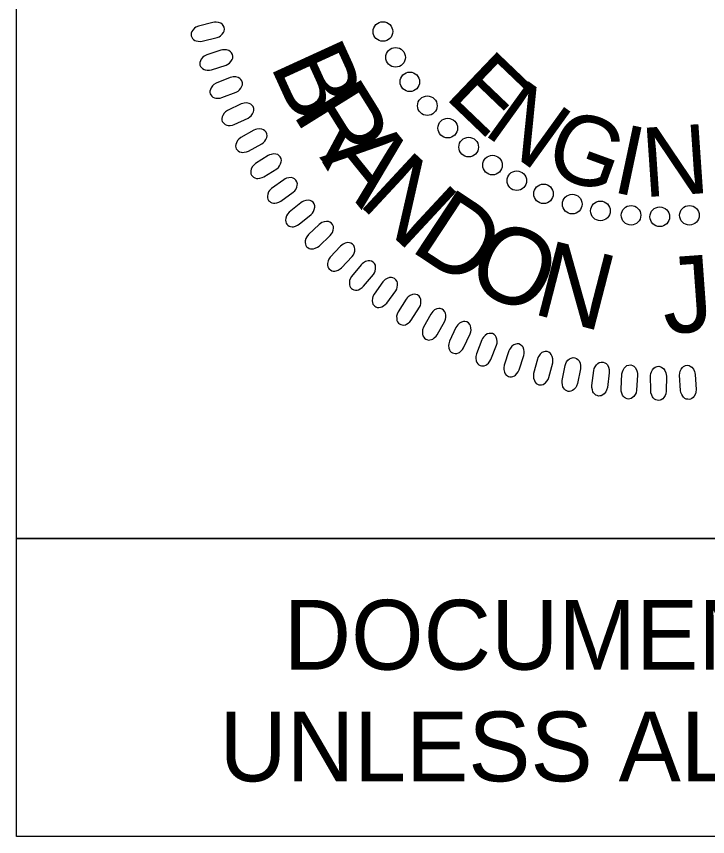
# Model space of a CAD drawing. Extents: x 18938 to 19565, y 6931 to 7973.
# Drawn here: x 19353.14 to 19360.49, y 7788.04 to 7796.76 of the extents above; entities that cross this region are included whole.
import ezdxf

# ---------------------------------------------------------------- set-up
doc = ezdxf.new("R2010")
doc.units = 0
for name, color, linetype in [('Old_Level_10', 7, 'Continuous'), ('Prop Pavement Schedule Description CELL', 7, 'Continuous'), ('Typical Hinge Slope Interstate CELL', 7, 'Continuous'), ('Typical Pavement Slope Information CELL', 7, 'Continuous')]:
    doc.layers.add(name, color=color, linetype=linetype)

# ---------------------------------------------------------------- blocks, each defined once
blk = doc.blocks.new('Brandon J. McInnis')
at = {"layer": 'Old_Level_10'}
for points in [[(-87.757, 42.228), (-88.945, 41.923), (-89.148, 41.832), (-89.271, 41.747), (-89.407, 41.596), (-89.489, 41.475), (-89.538, 41.346), (-89.551, 41.235), (-89.542, 41.121), (-89.495, 41.018), (-89.437, 40.91), (-89.353, 40.823), (-89.23, 40.747), (-89.138, 40.708), (-88.976, 40.68), (-88.787, 40.667), (-88.628, 40.685), (-87.408, 40.989), (-87.249, 41.053), (-87.126, 41.132), (-86.993, 41.258), (-86.886, 41.401), (-86.833, 41.515), (-86.814, 41.682), (-86.832, 41.832), (-86.907, 41.967), (-86.982, 42.056), (-87.11, 42.155), (-87.304, 42.228), (-87.495, 42.249), (-87.627, 42.245)], [(-87.103, 39.944), (-88.269, 39.565), (-88.467, 39.462), (-88.584, 39.37), (-88.71, 39.21), (-88.785, 39.083), (-88.826, 38.952), (-88.831, 38.841), (-88.816, 38.728), (-88.762, 38.628), (-88.696, 38.523), (-88.608, 38.442), (-88.48, 38.374), (-88.386, 38.341), (-88.223, 38.323), (-88.034, 38.322), (-87.875, 38.349), (-86.677, 38.73), (-86.523, 38.804), (-86.404, 38.89), (-86.281, 39.024), (-86.182, 39.174), (-86.136, 39.291), (-86.128, 39.459), (-86.155, 39.607), (-86.239, 39.737), (-86.319, 39.821), (-86.452, 39.911), (-86.651, 39.973), (-86.842, 39.981), (-86.975, 39.969)], [(-86.344, 37.707), (-87.485, 37.256), (-87.675, 37.14), (-87.786, 37.04), (-87.902, 36.873), (-87.969, 36.742), (-88.001, 36.609), (-88, 36.497), (-87.978, 36.385), (-87.918, 36.289), (-87.846, 36.188), (-87.752, 36.113), (-87.62, 36.053), (-87.524, 36.026), (-87.36, 36.019), (-87.172, 36.029), (-87.015, 36.067), (-85.844, 36.522), (-85.694, 36.605), (-85.581, 36.698), (-85.466, 36.84), (-85.377, 36.996), (-85.338, 37.116), (-85.34, 37.284), (-85.377, 37.431), (-85.469, 37.554), (-85.554, 37.633), (-85.693, 37.715), (-85.895, 37.763), (-86.087, 37.76), (-86.218, 37.74)], [(-85.444, 35.547), (-86.555, 35.025), (-86.737, 34.898), (-86.842, 34.791), (-86.947, 34.617), (-87.005, 34.483), (-87.029, 34.347), (-87.021, 34.236), (-86.992, 34.126), (-86.926, 34.033), (-86.847, 33.937), (-86.749, 33.868), (-86.614, 33.816), (-86.517, 33.796), (-86.353, 33.798), (-86.164, 33.821), (-86.011, 33.868), (-84.87, 34.396), (-84.726, 34.489), (-84.619, 34.589), (-84.513, 34.737), (-84.434, 34.898), (-84.403, 35.021), (-84.416, 35.188), (-84.462, 35.332), (-84.561, 35.45), (-84.651, 35.524), (-84.795, 35.597), (-84.999, 35.632), (-85.191, 35.617), (-85.321, 35.589)], [(-84.397, 33.398), (-85.473, 32.808), (-85.646, 32.67), (-85.744, 32.556), (-85.839, 32.377), (-85.888, 32.238), (-85.904, 32.102), (-85.888, 31.991), (-85.852, 31.883), (-85.78, 31.795), (-85.696, 31.704), (-85.594, 31.641), (-85.456, 31.598), (-85.357, 31.583), (-85.194, 31.596), (-85.008, 31.631), (-84.857, 31.687), (-83.752, 32.286), (-83.614, 32.388), (-83.514, 32.494), (-83.417, 32.649), (-83.349, 32.815), (-83.325, 32.939), (-83.348, 33.105), (-83.403, 33.246), (-83.51, 33.357), (-83.604, 33.425), (-83.752, 33.488), (-83.959, 33.511), (-84.149, 33.484), (-84.276, 33.448)], [(-83.241, 31.324), (-84.277, 30.666), (-84.442, 30.518), (-84.532, 30.399), (-84.615, 30.213), (-84.656, 30.073), (-84.663, 29.935), (-84.641, 29.825), (-84.597, 29.72), (-84.52, 29.636), (-84.431, 29.551), (-84.325, 29.495), (-84.184, 29.46), (-84.085, 29.452), (-83.922, 29.475), (-83.739, 29.521), (-83.592, 29.587), (-82.527, 30.254), (-82.396, 30.363), (-82.302, 30.477), (-82.215, 30.638), (-82.157, 30.807), (-82.142, 30.932), (-82.176, 31.097), (-82.239, 31.234), (-82.353, 31.338), (-82.451, 31.4), (-82.603, 31.454), (-82.81, 31.464), (-82.999, 31.425), (-83.123, 31.38)], [(-81.964, 29.349), (-82.957, 28.628), (-83.112, 28.469), (-83.196, 28.345), (-83.266, 28.154), (-83.298, 28.011), (-83.296, 27.873), (-83.267, 27.766), (-83.218, 27.662), (-83.136, 27.584), (-83.041, 27.505), (-82.931, 27.455), (-82.789, 27.429), (-82.689, 27.428), (-82.529, 27.461), (-82.349, 27.518), (-82.206, 27.593), (-81.185, 28.326), (-81.061, 28.444), (-80.974, 28.562), (-80.898, 28.728), (-80.851, 28.901), (-80.843, 29.026), (-80.887, 29.189), (-80.959, 29.322), (-81.079, 29.419), (-81.181, 29.474), (-81.336, 29.519), (-81.543, 29.516), (-81.729, 29.465), (-81.851, 29.413)], [(-80.561, 27.467), (-81.506, 26.685), (-81.651, 26.517), (-81.726, 26.388), (-81.785, 26.194), (-81.808, 26.049), (-81.798, 25.912), (-81.762, 25.806), (-81.706, 25.706), (-81.619, 25.633), (-81.519, 25.56), (-81.407, 25.517), (-81.264, 25.5), (-81.164, 25.505), (-81.005, 25.548), (-80.829, 25.617), (-80.692, 25.7), (-79.718, 26.496), (-79.602, 26.621), (-79.524, 26.745), (-79.458, 26.915), (-79.421, 27.091), (-79.421, 27.216), (-79.475, 27.376), (-79.556, 27.504), (-79.681, 27.593), (-79.787, 27.642), (-79.945, 27.677), (-80.151, 27.661), (-80.333, 27.598), (-80.452, 27.539)], [(-79.051, 25.697), (-79.945, 24.857), (-80.08, 24.68), (-80.146, 24.547), (-80.193, 24.349), (-80.206, 24.203), (-80.188, 24.066), (-80.145, 23.962), (-80.083, 23.867), (-79.991, 23.799), (-79.887, 23.732), (-79.773, 23.697), (-79.628, 23.689), (-79.53, 23.7), (-79.374, 23.753), (-79.202, 23.832), (-79.07, 23.925), (-78.149, 24.78), (-78.041, 24.912), (-77.97, 25.041), (-77.914, 25.215), (-77.889, 25.392), (-77.898, 25.517), (-77.962, 25.674), (-78.05, 25.796), (-78.181, 25.877), (-78.289, 25.92), (-78.449, 25.944), (-78.654, 25.915), (-78.831, 25.841), (-78.946, 25.774)], [(-77.315, 23.919), (-78.155, 23.024), (-78.278, 22.839), (-78.336, 22.702), (-78.37, 22.501), (-78.375, 22.354), (-78.348, 22.22), (-78.299, 22.12), (-78.23, 22.028), (-78.135, 21.966), (-78.027, 21.906), (-77.91, 21.877), (-77.766, 21.879), (-77.668, 21.895), (-77.516, 21.958), (-77.35, 22.048), (-77.224, 22.149), (-76.358, 23.06), (-76.258, 23.199), (-76.195, 23.332), (-76.151, 23.509), (-76.138, 23.687), (-76.154, 23.812), (-76.227, 23.963), (-76.323, 24.081), (-76.459, 24.154), (-76.569, 24.189), (-76.73, 24.204), (-76.933, 24.161), (-77.106, 24.077), (-77.216, 24.003)], [(-75.625, 22.389), (-76.408, 21.443), (-76.519, 21.25), (-76.568, 21.11), (-76.589, 20.908), (-76.584, 20.761), (-76.549, 20.628), (-76.494, 20.53), (-76.42, 20.443), (-76.322, 20.388), (-76.21, 20.335), (-76.092, 20.314), (-75.947, 20.324), (-75.85, 20.347), (-75.703, 20.419), (-75.542, 20.519), (-75.423, 20.628), (-74.616, 21.592), (-74.525, 21.736), (-74.471, 21.873), (-74.438, 22.053), (-74.435, 22.231), (-74.459, 22.356), (-74.542, 22.501), (-74.645, 22.612), (-74.785, 22.676), (-74.898, 22.705), (-75.059, 22.709), (-75.259, 22.655), (-75.427, 22.559), (-75.531, 22.479)], [(-73.844, 20.988), (-74.566, 19.995), (-74.664, 19.796), (-74.704, 19.652), (-74.714, 19.449), (-74.699, 19.303), (-74.655, 19.173), (-74.594, 19.079), (-74.515, 18.997), (-74.413, 18.947), (-74.298, 18.901), (-74.179, 18.888), (-74.035, 18.907), (-73.94, 18.936), (-73.798, 19.018), (-73.644, 19.128), (-73.532, 19.244), (-72.787, 20.256), (-72.705, 20.406), (-72.66, 20.546), (-72.638, 20.727), (-72.646, 20.906), (-72.678, 21.027), (-72.77, 21.169), (-72.88, 21.273), (-73.024, 21.328), (-73.138, 21.349), (-73.299, 21.344), (-73.495, 21.276), (-73.656, 21.171), (-73.756, 21.083)], [(-71.942, 19.575), (-72.6, 18.539), (-72.687, 18.334), (-72.717, 18.188), (-72.714, 17.984), (-72.69, 17.84), (-72.638, 17.713), (-72.572, 17.622), (-72.487, 17.546), (-72.382, 17.502), (-72.265, 17.463), (-72.145, 17.458), (-72.003, 17.486), (-71.909, 17.522), (-71.773, 17.611), (-71.626, 17.731), (-71.521, 17.854), (-70.842, 18.91), (-70.77, 19.066), (-70.733, 19.208), (-70.723, 19.39), (-70.742, 19.568), (-70.782, 19.688), (-70.882, 19.823), (-70.998, 19.919), (-71.146, 19.966), (-71.261, 19.98), (-71.421, 19.964), (-71.613, 19.885), (-71.766, 19.769), (-71.861, 19.676)], [(-69.925, 18.359), (-70.516, 17.285), (-70.589, 17.074), (-70.611, 16.927), (-70.594, 16.724), (-70.562, 16.581), (-70.502, 16.457), (-70.43, 16.372), (-70.34, 16.3), (-70.233, 16.264), (-70.114, 16.232), (-69.994, 16.234), (-69.854, 16.271), (-69.763, 16.312), (-69.632, 16.411), (-69.493, 16.539), (-69.396, 16.668), (-68.784, 17.766), (-68.722, 17.925), (-68.694, 18.069), (-68.696, 18.252), (-68.726, 18.428), (-68.773, 18.545), (-68.882, 18.673), (-69.003, 18.763), (-69.153, 18.8), (-69.269, 18.807), (-69.429, 18.781), (-69.615, 18.689), (-69.761, 18.565), (-69.849, 18.466)], [(-67.865, 17.253), (-68.388, 16.143), (-68.447, 15.929), (-68.46, 15.78), (-68.431, 15.578), (-68.389, 15.438), (-68.322, 15.318), (-68.245, 15.237), (-68.151, 15.172), (-68.041, 15.142), (-67.921, 15.118), (-67.801, 15.128), (-67.663, 15.174), (-67.575, 15.22), (-67.45, 15.327), (-67.319, 15.463), (-67.231, 15.598), (-66.689, 16.732), (-66.637, 16.895), (-66.619, 17.04), (-66.631, 17.223), (-66.673, 17.397), (-66.728, 17.511), (-66.844, 17.632), (-66.971, 17.714), (-67.123, 17.741), (-67.239, 17.74), (-67.396, 17.705), (-67.576, 17.602), (-67.714, 17.468), (-67.796, 17.364)], [(-65.738, 16.245), (-66.19, 15.104), (-66.236, 14.886), (-66.239, 14.737), (-66.197, 14.538), (-66.147, 14.4), (-66.072, 14.285), (-65.99, 14.209), (-65.892, 14.149), (-65.782, 14.127), (-65.659, 14.111), (-65.54, 14.127), (-65.406, 14.182), (-65.321, 14.234), (-65.203, 14.348), (-65.081, 14.493), (-65.001, 14.633), (-64.532, 15.799), (-64.49, 15.964), (-64.481, 16.11), (-64.505, 16.292), (-64.557, 16.463), (-64.619, 16.573), (-64.742, 16.687), (-64.875, 16.76), (-65.028, 16.778), (-65.144, 16.77), (-65.298, 16.725), (-65.472, 16.611), (-65.601, 16.468), (-65.676, 16.359)], [(-63.529, 15.342), (-63.909, 14.176), (-63.941, 13.955), (-63.935, 13.807), (-63.88, 13.61), (-63.822, 13.476), (-63.739, 13.366), (-63.653, 13.296), (-63.552, 13.242), (-63.439, 13.226), (-63.316, 13.218), (-63.198, 13.242), (-63.068, 13.305), (-62.986, 13.362), (-62.876, 13.484), (-62.764, 13.636), (-62.693, 13.78), (-62.297, 14.973), (-62.266, 15.141), (-62.266, 15.288), (-62.302, 15.467), (-62.365, 15.635), (-62.433, 15.741), (-62.563, 15.846), (-62.7, 15.912), (-62.854, 15.92), (-62.969, 15.904), (-63.121, 15.849), (-63.286, 15.725), (-63.406, 15.575), (-63.475, 15.461)], [(-61.196, 14.669), (-61.502, 13.481), (-61.52, 13.26), (-61.505, 13.111), (-61.438, 12.919), (-61.371, 12.788), (-61.282, 12.684), (-61.191, 12.619), (-61.087, 12.572), (-60.974, 12.563), (-60.85, 12.563), (-60.734, 12.594), (-60.608, 12.665), (-60.53, 12.726), (-60.428, 12.855), (-60.325, 13.014), (-60.264, 13.163), (-59.943, 14.378), (-59.923, 14.548), (-59.932, 14.694), (-59.979, 14.871), (-60.053, 15.034), (-60.127, 15.136), (-60.265, 15.233), (-60.404, 15.289), (-60.559, 15.288), (-60.673, 15.266), (-60.821, 15.201), (-60.978, 15.066), (-61.089, 14.909), (-61.149, 14.791)], [(-57.674, 13.882), (-57.905, 12.677), (-57.982, 12.468), (-58.06, 12.341), (-58.202, 12.195), (-58.318, 12.106), (-58.443, 12.049), (-58.553, 12.029), (-58.667, 12.031), (-58.773, 12.071), (-58.885, 12.123), (-58.977, 12.201), (-59.061, 12.319), (-59.105, 12.409), (-59.143, 12.568), (-59.168, 12.756), (-59.16, 12.917), (-58.931, 14.152), (-58.877, 14.315), (-58.807, 14.443), (-58.689, 14.583), (-58.553, 14.699), (-58.442, 14.76), (-58.277, 14.789), (-58.126, 14.78), (-57.987, 14.713), (-57.894, 14.644), (-57.787, 14.523), (-57.702, 14.334), (-57.669, 14.144), (-57.665, 14.012)], [(-55.308, 13.556), (-55.463, 12.339), (-55.527, 12.126), (-55.596, 11.993), (-55.729, 11.839), (-55.839, 11.743), (-55.96, 11.677), (-56.069, 11.651), (-56.183, 11.646), (-56.291, 11.68), (-56.407, 11.724), (-56.503, 11.796), (-56.593, 11.909), (-56.643, 11.996), (-56.691, 12.153), (-56.728, 12.338), (-56.73, 12.499), (-56.58, 13.746), (-56.536, 13.912), (-56.474, 14.045), (-56.365, 14.192), (-56.237, 14.317), (-56.13, 14.383), (-55.967, 14.423), (-55.816, 14.424), (-55.673, 14.365), (-55.575, 14.303), (-55.461, 14.188), (-55.365, 14.005), (-55.32, 13.818), (-55.307, 13.686)], [(-52.991, 13.358), (-53.069, 12.134), (-53.119, 11.918), (-53.18, 11.781), (-53.303, 11.619), (-53.407, 11.515), (-53.524, 11.443), (-53.631, 11.409), (-53.745, 11.397), (-53.854, 11.425), (-53.972, 11.461), (-54.072, 11.527), (-54.171, 11.634), (-54.226, 11.717), (-54.283, 11.871), (-54.332, 12.054), (-54.344, 12.215), (-54.272, 13.469), (-54.239, 13.637), (-54.185, 13.773), (-54.086, 13.927), (-53.965, 14.059), (-53.863, 14.133), (-53.703, 14.182), (-53.552, 14.193), (-53.405, 14.143), (-53.305, 14.087), (-53.184, 13.98), (-53.075, 13.803), (-53.019, 13.619), (-52.998, 13.489)], [(-48.27, 13.409), (-48.194, 12.184), (-48.217, 11.963), (-48.26, 11.82), (-48.362, 11.644), (-48.452, 11.528), (-48.559, 11.442), (-48.661, 11.396), (-48.772, 11.369), (-48.884, 11.382), (-49.006, 11.404), (-49.114, 11.457), (-49.225, 11.551), (-49.29, 11.626), (-49.366, 11.772), (-49.437, 11.947), (-49.469, 12.105), (-49.556, 13.358), (-49.544, 13.529), (-49.507, 13.671), (-49.427, 13.836), (-49.325, 13.982), (-49.232, 14.068), (-49.08, 14.138), (-48.932, 14.167), (-48.78, 14.136), (-48.673, 14.093), (-48.539, 14.002), (-48.41, 13.84), (-48.331, 13.664), (-48.293, 13.537)], [(-50.637, 13.286), (-50.638, 12.059), (-50.676, 11.841), (-50.728, 11.7), (-50.84, 11.531), (-50.937, 11.421), (-51.05, 11.341), (-51.154, 11.302), (-51.266, 11.282), (-51.378, 11.302), (-51.498, 11.332), (-51.603, 11.391), (-51.707, 11.492), (-51.767, 11.571), (-51.834, 11.721), (-51.894, 11.9), (-51.916, 12.06), (-51.923, 13.316), (-51.901, 13.486), (-51.856, 13.626), (-51.766, 13.785), (-51.654, 13.925), (-51.556, 14.005), (-51.4, 14.064), (-51.25, 14.084), (-51.101, 14.044), (-50.996, 13.994), (-50.868, 13.895), (-50.75, 13.725), (-50.682, 13.545), (-50.653, 13.416)]]:
    blk.add_lwpolyline(points, close=True, dxfattribs=at)
for centre in [(-73.84, 41.476), (-72.805, 39.364), (-71.636, 37.36), (-70.203, 35.407), (-68.532, 33.574), (-66.82, 32.02), (-64.87, 30.546), (-62.88, 29.27), (-60.69, 28.194), (-58.342, 27.356), (-56.033, 26.798), (-53.525, 26.439), (-51.176, 26.318), (-48.747, 26.437)]:
    blk.add_circle(centre, 0.801, dxfattribs=at)
for s, height, rotation, p in [('B', 6.236, 294.5897, (-83.122, 38.747)), ('E', 5.669, 316.26559, (-68.882, 36.126)), ('R', 6.236, 301.86473, (-81.311, 34.79)), ('N', 5.669, 324.20538, (-65.747, 33.17)), ('G', 5.669, 340.08498, (-60.853, 30.072)), ('I', 5.669, 348.02477, (-55.225, 28.382)), ('N', 5.669, 3.90437, (-52.471, 27.91)), ('A', 6.236, 308.98157, (-79.069, 31.172)), ('N', 6.236, 317.09274, (-75.99, 27.424)), ('D', 6.236, 326.58243, (-71.76, 23.643)), ('O', 6.236, 335.45066, (-67.294, 20.785)), ('N', 6.236, 345.5505, (-61.742, 18.413)), ('J', 6.236, 4.1457, (-50.791, 16.721))]:
    blk.add_text(s, height=height, rotation=rotation, dxfattribs=at).set_placement(p)

msp = doc.modelspace()

# ---------------------------------------------------------------- linework, layer by layer
at = {"layer": 'Typical Hinge Slope Interstate CELL'}
for p, q in [((19353.1353, 7788.0383), (19353.1353, 7791.211)), ((19353.1353, 7791.211), (19380.142, 7791.211)), ((19380.142, 7788.0383), (19353.1353, 7788.0383))]:
    msp.add_line(p, q, dxfattribs=at)
at = {"layer": 'Typical Pavement Slope Information CELL'}
msp.add_lwpolyline([(19353.1353, 7806.2555), (19366.642, 7806.2555), (19366.642, 7791.211), (19353.1353, 7791.211)], close=True, dxfattribs=at)

# ---------------------------------------------------------------- block references
at = {"layer": 'Prop Pavement Schedule Description CELL', "xscale": 0.13, "yscale": 0.13}
msp.add_blockref('Brandon J. McInnis', (19366.6353, 7791.211), dxfattribs=at)

# ---------------------------------------------------------------- texts
at = {"layer": 'Typical Hinge Slope Interstate CELL'}
for s, p in [('DOCUMENT NOT CONSIDERED FINAL', (19355.98, 7789.8143)), ('UNLESS ALL SIGNATURES COMPLETED', (19355.2954, 7788.6262))]:
    msp.add_text(s, height=0.742545, dxfattribs=at).set_placement(p)

doc.saveas('drawing.dxf')
